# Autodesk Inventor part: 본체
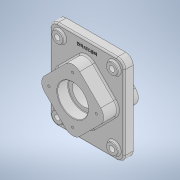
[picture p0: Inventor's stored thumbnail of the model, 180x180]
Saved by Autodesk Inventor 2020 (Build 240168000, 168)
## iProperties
Created: 2021-07
Part Number: 본체
Material: 일반
Document SubType Name: Modeling
Designer: Owner
Density: 1 g/cm^3
Appearance: 기본값
Mass: 807.977 g
Surface Area: 961.758 cm^2
Volume: 807.977 cm^3
Author: Owner
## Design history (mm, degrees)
sketch "스케치1"
  geometry: L1 (75, -90)-(-75, -90); L2 (-75, -90)-(-75, 90); L3 (-75, 90)-(75, 90); L4 (75, 90)-(75, -90); L5 (75, -90)-(-75, 90); L6 (-75, -90)-(75, 90); 1 further point
  constraints: 12 end point, 2 midpoint, 2 parallel, 1 horizontal, 1 perpendicular
  dimensions: "d0" = 150 distance of L2.end L3.end; "d1" = 180 distance of L3.end L1.start
extrude "돌출1" new body sketch "스케치1" stored distance "d2" = 18; taper "d3" = 0 deg
node "작업 평면1"
sketch "스케치2"
  geometry: L1 (-70.711, 0)-(0, 70.711); L2 (0, 70.711)-(70.711, 0); L3 (70.711, 0)-(0, -70.711); L4 (0, -70.711)-(-70.711, 0); L5 (-70.711, 0)-(70.711, 0); L6 (0, 70.711)-(0, -70.711); 3 further points
  constraints: 12 end point, 4 midpoint, 2 parallel, 1 horizontal alignment, 1 perpendicular, 1 vertical alignment
  dimensions: "d5" = 100 distance of L3.end L1.start
extrude "돌출2" join sketch "스케치2" distance "d6" = 70; taper "d7" = 0 deg
fillet "모깎기1" dims "d8" = 15
fillet "모깎기2" dims "d9" = 20
sketch "스케치3"
  geometry: C1 r 11 at (-55, 70); 1 further point
  constraints: 1 centre point
  dimensions: "d10" = 22 diameter of C1; "d11" = 55 horizontal distance of point (0, 0) C1.centre; "d12" = 70 vertical distance of point (0, 0) C1.centre
extrude "돌출3" join sketch "스케치3" distance "d13" = 5; taper "d14" = 0 deg
sketch "스케치4"
  geometry: C1 r 11 at (0, 0) reference; 2 further points
  constraints: 1 coincident
hole "구멍1" sketch "스케치4" at (0, 0) diameter "d15" = 11; stored, may be unused: countersink angle "d19" = 82 deg, drill point angle "d21" = 0 deg; dims "d16" = 8, "d17" = 3.023, "d18" = 2, "d20" = 11
sketch "스케치5"
  geometry: C1 r 31 at (0, 0); 1 further point
  constraints: 1 centre point, 1 coincident
  dimensions: "d28" = 62 diameter of C1
extrude "돌출4" cut sketch "스케치5" distance "d29" = 22; taper "d30" = 0 deg
sketch "스케치6"
  geometry: C1 r 31 at (0, 0); 1 further point
  constraints: 1 centre point, 1 coincident
  dimensions: "d31" = 62 diameter of C1
extrude "돌출5" cut sketch "스케치6" distance "d32" = 22; taper "d33" = 0 deg
sketch "스케치7"
  geometry: C1 r 22.5 at (0, 0); 1 further point
  constraints: 1 centre point, 1 coincident
  dimensions: "d34" = 45 diameter of C1
extrude "돌출6" cut sketch "스케치7" stored distance "d35" = 25; taper "d36" = 0 deg
sketch "스케치8" dims "d37" = 96
  geometry: 3 further points
  constraints: 2 vertical alignment, 1 coincident, 2 other
hole "구멍2" sketch "스케치8" at (0, 48) diameter "d38" = 4.917; stored, may be unused: countersink angle "d42" = 82 deg, drill point angle "d44" = 118 deg; dims "d39" = 10, "d40" = 3.023, "d41" = 2, "d43" = 13
sketch "스케치9" dims "d48" = 96
  geometry: 3 further points
  constraints: 2 vertical alignment, 1 coincident, 2 other
hole "구멍3" sketch "스케치9" at (0, 48) diameter "d49" = 4.917; stored, may be unused: countersink angle "d53" = 82 deg, drill point angle "d55" = 118 deg; dims "d50" = 10, "d51" = 3.023, "d52" = 2, "d54" = 13
chamfer "모따기1" distance "d59" = 1; stored, may be unused: second distance "d60" = 2, angle "d61" = 45 deg
fillet "모깎기3" dims "d62" = 1
fillet "모깎기4" dims "d63" = 3
sketch "스케치10"
  geometry: L1 (-38.637, 91.493)-(38.637, 91.493); L2 (38.637, 91.493)-(38.637, 58.507); L3 (38.637, 58.507)-(-38.637, 58.507); L4 (-38.637, 58.507)-(-38.637, 91.493); L5 (60, 90)-(-60, 90) reference; 4 further points
  constraints: 2 midpoint, 2 vertical alignment, 1 horizontal alignment, 2 other
  dimensions: "d64" = 15 distance from line of L5 point (0, 75)
feature "엠보싱1" sketch "스케치10" dims "d0" = 150, "d1" = 180, "d65" = 0.5, "d66" = 0
node "솔리드1"
pattern_linear "직사각형 패턴1" dims "d24" = 110, "d27" = 140
pattern_circular "원형 패턴1" dims angle "d46" = 360 deg
pattern_circular "원형 패턴2" dims angle "d57" = 360 deg
feature "A9D066F2-1C7D-4E18-AEED-F7BC21143FA4" dims "d15" = 11, "d16" = 8, "d17" = 3.023, "d18" = 2, "d19" = 82 deg, "d20" = 11, "d21" = 0
other parameters: "d4" = 23
